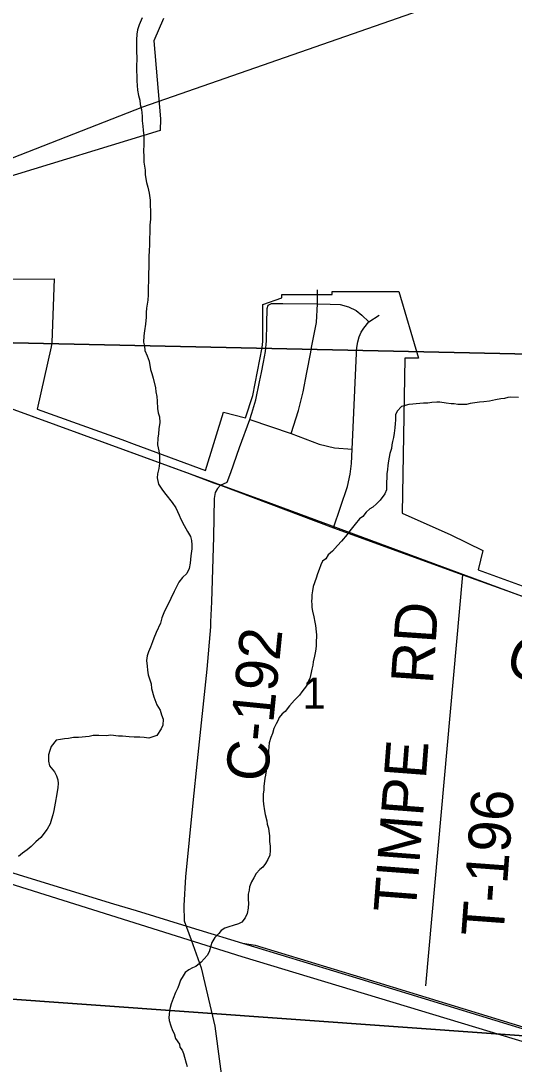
# Model space of a CAD drawing. Extents: x 0 to 34, y 0 to 22.
# Drawn here: x 25.144 to 25.81, y 18.872 to 20.279 of the extents above; entities that cross this region are included whole.
import ezdxf

# ---------------------------------------------------------------- set-up
doc = ezdxf.new("R2010")
doc.units = 0
for name, color, linetype in [('GM_X_City_Street', 7, 'Continuous'), ('GM_X_County_Road', 7, 'Continuous'), ('GM_X_County_Road_Text', 7, 'Continuous'), ('GM_X_Minor_River', 7, 'Continuous'), ('GM_X_Rail_Line', 7, 'Continuous'), ('GM_X_Section', 7, 'Continuous'), ('GM_X_Section_Text', 7, 'Continuous'), ('GM_X_Township_Road', 7, 'Continuous'), ('GM_X_Township_Road_Text', 7, 'Continuous')]:
    doc.layers.add(name, color=color, linetype=linetype)

msp = doc.modelspace()

# ---------------------------------------------------------------- linework, layer by layer
at = {"layer": 'GM_X_City_Street'}
for points in [[(25.3368, 20.282), (25.3235, 20.252), (25.3327, 20.1469), (25.3319, 20.1309), (25.1177, 20.0653)], [(25.1107, 19.9304), (25.1891, 19.9311), (25.186, 19.8449), (25.1851, 19.8393), (25.1663, 19.7552), (25.2805, 19.7144), (25.2972, 19.7081), (25.3934, 19.6725), (25.4177, 19.7511), (25.4472, 19.7433), (25.457, 19.7736), (25.4695, 19.8382), (25.4705, 19.8462), (25.4705, 19.8965), (25.4963, 19.9051), (25.4964, 19.91), (25.5366, 19.91), (25.564, 19.91), (25.564, 19.9138), (25.6541, 19.9138), (25.6804, 19.8237), (25.6621, 19.824), (25.6584, 19.6147), (25.724, 19.5855), (25.7672, 19.5644), (25.7608, 19.5385), (26.0181, 19.4449)]]:
    msp.add_lwpolyline(points, dxfattribs=at)
at = {"layer": 'GM_X_County_Road'}
for points in [[(25.0113, 19.7995), (25.3711, 19.6682), (25.4041, 19.6559)], [(25.4135, 19.6524), (25.4093, 19.648), (25.4061, 19.6427), (25.405, 19.6347), (25.4039, 19.583), (25.4014, 19.4953), (25.4001, 19.4683)], [(25.4041, 19.6559), (25.4135, 19.6524), (25.5658, 19.595)], [(25.5658, 19.595), (25.7402, 19.5316), (26.0796, 19.4097), (26.0866, 19.4072)], [(25.4001, 19.4683), (25.3998, 19.4615), (25.395, 19.4046), (25.3819, 19.2807), (25.3763, 19.2239)], [(25.3763, 19.2239), (25.3665, 19.1241), (25.3639, 19.0857), (25.3644, 19.0648), (25.3738, 19.0391)], [(25.3738, 19.0391), (25.3876, 19.0014), (25.4057, 18.9229), (25.4261, 18.7706), (25.4348, 18.7435), (25.5481, 18.6163), (25.5629, 18.5929), (25.567, 18.4152)]]:
    msp.add_lwpolyline(points, dxfattribs=at)
at = {"layer": 'GM_X_Minor_River'}
for points in [[(25.308, 20.2832), (25.3037, 20.2734), (25.3017, 20.2666), (25.3005, 20.2609), (25.3001, 20.2533), (25.3, 20.245), (25.3003, 20.2389), (25.3005, 20.2279), (25.3, 20.2176), (25.3004, 20.2119), (25.3006, 20.204), (25.3006, 20.1979), (25.3009, 20.1918), (25.3016, 20.1854), (25.303, 20.1781), (25.3045, 20.172), (25.3051, 20.1663), (25.307, 20.1595), (25.308, 20.1504), (25.3079, 20.1439), (25.3086, 20.1367), (25.3093, 20.1314), (25.31, 20.1238), (25.3099, 20.1181), (25.3102, 20.1112), (25.3098, 20.104), (25.31, 20.0953), (25.3103, 20.0885), (25.311, 20.0831), (25.3117, 20.0774), (25.312, 20.0714), (25.3138, 20.0611), (25.3156, 20.0546), (25.3174, 20.0466), (25.3185, 20.0371), (25.3188, 20.0295), (25.3191, 20.0231)], [(25.3191, 20.0231), (25.3189, 20.0113), (25.3181, 20.0033), (25.3178, 19.9756), (25.3173, 19.9699), (25.3168, 19.9597), (25.3167, 19.9468), (25.3162, 19.9381), (25.3159, 19.9092), (25.3154, 19.902), (25.3138, 19.8914), (25.3133, 19.8853), (25.3133, 19.8793), (25.3124, 19.8698), (25.3112, 19.8607), (25.3103, 19.8539), (25.3098, 19.8455), (25.3109, 19.8402), (25.3116, 19.8341), (25.3146, 19.8269), (25.3171, 19.82), (25.3189, 19.8086), (25.3207, 19.8033), (25.3229, 19.7968), (25.3258, 19.7838), (25.3265, 19.7785), (25.3276, 19.7724), (25.3279, 19.766), (25.3286, 19.7561), (25.3296, 19.75), (25.3311, 19.7447), (25.3318, 19.7371), (25.3305, 19.7284), (25.3301, 19.7219), (25.3289, 19.7162), (25.3287, 19.7068), (25.3302, 19.6988), (25.3312, 19.6923), (25.3311, 19.6821), (25.3303, 19.6752), (25.3287, 19.668), (25.3282, 19.6627), (25.33, 19.654), (25.3353, 19.6459), (25.3397, 19.6398), (25.3484, 19.6291), (25.3532, 19.6218), (25.3576, 19.6123), (25.3602, 19.6066), (25.3643, 19.5982), (25.3692, 19.5902), (25.3729, 19.5833), (25.3743, 19.578), (25.375, 19.5723), (25.375, 19.5666), (25.3737, 19.5571), (25.3728, 19.5476), (25.3712, 19.5404), (25.3681, 19.5336), (25.3624, 19.528), (25.3574, 19.5216), (25.3539, 19.5144), (25.3508, 19.5091), (25.3465, 19.4997), (25.3372, 19.4804), (25.3344, 19.4736), (25.3325, 19.4664), (25.3266, 19.454), (25.3235, 19.4464), (25.3216, 19.4411), (25.3192, 19.4339), (25.3165, 19.4279), (25.3145, 19.4222), (25.3137, 19.4161), (25.3147, 19.4085), (25.3151, 19.4032), (25.3161, 19.3968), (25.3198, 19.3846), (25.3205, 19.3785), (25.3237, 19.3671), (25.3278, 19.3564), (25.3319, 19.3491), (25.3341, 19.3427), (25.3363, 19.3369), (25.3355, 19.329), (25.3335, 19.3237), (25.3277, 19.315), (25.317, 19.3113), (25.3106, 19.3122), (25.3049, 19.3126), (25.297, 19.3127), (25.2905, 19.3131), (25.2814, 19.314), (25.2761, 19.314), (25.2655, 19.3153), (25.2594, 19.3146), (25.2492, 19.3151), (25.2416, 19.3148), (25.2363, 19.3137), (25.2222, 19.3123), (25.2154, 19.3124)], [(25.7095, 19.7646), (25.7053, 19.7646), (25.6985, 19.7639), (25.6932, 19.7632), (25.6871, 19.7633), (25.6822, 19.7626), (25.6772, 19.7622), (25.6731, 19.7619), (25.6674, 19.7612), (25.6624, 19.7601), (25.6575, 19.7587), (25.6517, 19.7526), (25.6497, 19.7474), (25.6493, 19.7401), (25.6489, 19.7356), (25.6484, 19.7299), (25.6476, 19.7227), (25.6467, 19.717), (25.6456, 19.7117), (25.6447, 19.7068), (25.6443, 19.7022), (25.6419, 19.6951), (25.6399, 19.6856), (25.6391, 19.6791), (25.6387, 19.6738), (25.6378, 19.6681), (25.6378, 19.664), (25.6373, 19.6552), (25.6372, 19.6465), (25.6349, 19.6408), (25.6287, 19.6322), (25.6237, 19.6273), (25.6191, 19.6228), (25.6149, 19.6206), (25.6099, 19.6161), (25.6053, 19.6104), (25.6011, 19.607), (25.595, 19.5999), (25.5915, 19.5954), (25.588, 19.5912), (25.5842, 19.586), (25.5769, 19.5769), (25.5715, 19.5713), (25.5646, 19.5634), (25.5585, 19.5585), (25.5554, 19.5532), (25.5512, 19.5499), (25.5488, 19.545), (25.5465, 19.5389), (25.5445, 19.5332), (25.5425, 19.5272), (25.5386, 19.5158), (25.5374, 19.5102), (25.5366, 19.5045), (25.5366, 19.5003), (25.5361, 19.4961), (25.5365, 19.4916), (25.5368, 19.4874), (25.5375, 19.4825), (25.5393, 19.4752), (25.5407, 19.468), (25.5414, 19.4631), (25.5425, 19.4547), (25.5428, 19.4505), (25.5427, 19.4395), (25.5423, 19.4353), (25.5414, 19.4285), (25.5402, 19.4221), (25.5386, 19.4145), (25.5378, 19.4099), (25.5366, 19.4046), (25.5358, 19.3997), (25.5338, 19.3918), (25.5315, 19.3869), (25.5295, 19.3819), (25.523, 19.374), (25.5199, 19.3695), (25.5134, 19.3624), (25.5064, 19.3549), (25.5007, 19.3473), (25.4965, 19.3443), (25.4926, 19.3394), (25.491, 19.3349), (25.4887, 19.3308), (25.4856, 19.3243), (25.4836, 19.3175), (25.4813, 19.3122), (25.4793, 19.305), (25.4785, 19.2994), (25.4781, 19.2944), (25.4776, 19.2876), (25.4768, 19.2831), (25.476, 19.277), (25.4755, 19.2728), (25.4751, 19.2671), (25.4743, 19.2614), (25.4735, 19.2573), (25.473, 19.2531), (25.4718, 19.2467), (25.4718, 19.241), (25.471, 19.2364)], [(25.8154, 19.771), (25.8052, 19.7711), (25.801, 19.7708), (25.7964, 19.7697), (25.7915, 19.769), (25.7843, 19.7679), (25.7763, 19.7657), (25.7687, 19.7651), (25.763, 19.7644), (25.7501, 19.7626), (25.7451, 19.7615), (25.7334, 19.7616), (25.7288, 19.7621), (25.7246, 19.7621), (25.7178, 19.7633), (25.7095, 19.7646)], [(25.2154, 19.3124), (25.2085, 19.311), (25.2029, 19.3103), (25.1975, 19.3096), (25.1918, 19.3085), (25.1853, 19.3002), (25.1833, 19.2949), (25.1817, 19.2889), (25.1816, 19.2801), (25.1827, 19.274), (25.1895, 19.266), (25.1924, 19.2607), (25.1943, 19.2553), (25.1946, 19.25), (25.1941, 19.2447), (25.1929, 19.236), (25.1905, 19.2235), (25.1889, 19.2136), (25.1873, 19.2079), (25.1857, 19.2019), (25.1837, 19.1958), (25.1798, 19.1887), (25.1714, 19.1774), (25.1645, 19.1714), (25.158, 19.1654), (25.1526, 19.1609), (25.1465, 19.156), (25.1411, 19.1519)], [(25.471, 19.2364), (25.4709, 19.2319), (25.4712, 19.2273), (25.4716, 19.2224), (25.473, 19.2132), (25.4737, 19.2083), (25.4762, 19.1999), (25.4766, 19.1954), (25.4784, 19.19), (25.4787, 19.1859), (25.4794, 19.1794), (25.4797, 19.1718), (25.4804, 19.1657), (25.4803, 19.1596), (25.4799, 19.1536), (25.4772, 19.1475), (25.4741, 19.1423), (25.4706, 19.1374), (25.4664, 19.134), (25.4618, 19.1287), (25.4583, 19.1227), (25.4552, 19.1174), (25.4528, 19.1106), (25.452, 19.1064), (25.4508, 19.1007), (25.4507, 19.0939), (25.4514, 19.0886), (25.4506, 19.0821), (25.4494, 19.0749), (25.4467, 19.0689), (25.4421, 19.0633), (25.4379, 19.061), (25.4306, 19.0588), (25.4249, 19.0566), (25.4192, 19.0548), (25.4146, 19.0518), (25.4111, 19.0476), (25.4058, 19.0424), (25.4019, 19.0356), (25.4003, 19.0311), (25.398, 19.0231), (25.3956, 19.0182), (25.3872, 19.0092), (25.3803, 19.0032), (25.3757, 19.0013), (25.3708, 18.9987), (25.3658, 18.9954), (25.3631, 18.9905), (25.3596, 18.9848), (25.3576, 18.9795), (25.3561, 18.9746), (25.3526, 18.9682), (25.3498, 18.9602), (25.3471, 18.9531), (25.3455, 18.9481), (25.3447, 18.944), (25.3443, 18.9387), (25.3439, 18.9345), (25.3442, 18.9303), (25.3464, 18.9231), (25.3486, 18.917), (25.3508, 18.9128), (25.353, 18.9063), (25.3582, 18.8987), (25.3586, 18.8945), (25.3616, 18.8903), (25.3634, 18.8861), (25.3649, 18.8811), (25.3674, 18.8731), (25.3685, 18.8682)]]:
    msp.add_lwpolyline(points, dxfattribs=at)
at = {"layer": 'GM_X_Rail_Line'}
for points in [[(24.6857, 19.9193), (25.3089, 20.1629), (25.713, 20.3036), (25.9724, 20.3916), (26.54, 20.6067), (26.7751, 20.7), (27.3361, 20.9)], [(24.6857, 19.9193), (25.0148, 19.7985), (25.4772, 19.6296), (26.0332, 19.4244), (26.618, 19.2083), (27.1754, 19.0083), (27.8265, 18.7785), (28.397, 18.5695), (29.2915, 18.2251), (29.5147, 18.1387)], [(24.1704, 19.5327), (24.2425, 19.4909), (24.3878, 19.4135), (24.5787, 19.3195), (24.7175, 19.2589), (24.8405, 19.2105), (24.9746, 19.1639), (25.4423, 19.0168), (26.3104, 18.7542), (27.1506, 18.4971), (27.9899, 18.2401), (28.4862, 18.088)], [(25.1011, 19.1396), (25.1536, 19.1235), (25.2694, 19.0879), (25.2996, 19.0787), (25.3683, 19.0577), (25.4595, 19.0299), (25.6015, 18.9867), (25.8055, 18.9242), (25.847, 18.9114), (25.9704, 18.8734), (26.0653, 18.8446), (26.2947, 18.7744), (26.4597, 18.7238), (26.5651, 18.6918), (26.6458, 18.6671), (26.7252, 18.6428), (26.8299, 18.611), (26.9128, 18.5857), (26.9875, 18.5627), (27.1965, 18.4991)], [(25.4438, 19.0347), (25.4601, 19.0321), (25.6021, 18.989), (25.8062, 18.9265), (25.8477, 18.9137), (25.9711, 18.8756), (26.066, 18.8468), (26.2954, 18.7766), (26.4604, 18.726), (26.5658, 18.694), (26.6465, 18.6693), (26.6813, 18.6587), (26.7055, 18.6488)]]:
    msp.add_lwpolyline(points, dxfattribs=at)
at = {"layer": 'GM_X_Section'}
for points in [[(26.1064, 20.8349), (26.1071, 20.822), (26.0975, 19.8234), (25.0925, 19.8455), (25.1198, 20.8277)], [(25.0077, 19.8483), (25.0925, 19.8455), (26.0975, 19.8234), (26.0616, 18.9227), (26.0607, 18.8928), (24.9624, 18.9716)], [(26.0607, 18.8928), (26.0171, 17.9156), (26.0158, 17.891), (24.9267, 17.9117), (24.9624, 18.9716)]]:
    msp.add_lwpolyline(points, close=True, dxfattribs=at)
at = {"layer": 'GM_X_Township_Road'}
msp.add_line((25.6906, 18.9772), (25.7402, 19.5316), dxfattribs=at)
for points in [[(25.5352, 19.8319), (25.5364, 19.8383), (25.543, 19.8722), (25.5443, 19.8971), (25.5442, 19.9162)], [(25.4687, 19.8047), (25.4715, 19.8183), (25.4741, 19.8331), (25.4757, 19.8473), (25.4762, 19.8705), (25.4763, 19.8908), (25.4778, 19.8956)], [(25.4778, 19.8956), (25.4824, 19.8975), (25.4974, 19.8978), (25.5443, 19.8971), (25.5612, 19.8968), (25.5747, 19.8961), (25.5861, 19.8931), (25.5964, 19.8881), (25.6043, 19.882), (25.6135, 19.873)], [(25.5971, 19.8335), (25.5974, 19.8383), (25.5985, 19.8461), (25.6007, 19.8529), (25.6034, 19.859), (25.6066, 19.8643), (25.6135, 19.873), (25.6275, 19.882)], [(25.5086, 19.7222), (25.5186, 19.7531), (25.5248, 19.7783), (25.5298, 19.8045), (25.5352, 19.8319)], [(25.5658, 19.595), (25.5849, 19.6509), (25.5882, 19.6674), (25.5902, 19.6816), (25.591, 19.7013), (25.5919, 19.7203), (25.5945, 19.7809), (25.5969, 19.8307), (25.5971, 19.8335)], [(25.4135, 19.6524), (25.4223, 19.6565), (25.4273, 19.6699), (25.4393, 19.7033), (25.453, 19.741), (25.4558, 19.7496), (25.4612, 19.7678), (25.4662, 19.7921), (25.4687, 19.8047)], [(25.453, 19.741), (25.5086, 19.7222), (25.5467, 19.7079), (25.5674, 19.703), (25.591, 19.7013)]]:
    msp.add_lwpolyline(points, dxfattribs=at)

# ---------------------------------------------------------------- texts
at = {"layer": 'GM_X_County_Road_Text'}
for s, rotation, p in [('C-192', 84.2806, (25.4766, 19.251)), ('C-20', 341.1304, (25.7946, 19.4002))]:
    msp.add_text(s, height=0.05682, rotation=rotation, dxfattribs=at).set_placement(p)
at = {"layer": 'GM_X_Section_Text'}
msp.add_text('1', height=0.0419, rotation=0, dxfattribs=at).set_placement((25.524, 19.3512))
at = {"layer": 'GM_X_Township_Road_Text'}
for s, rotation, p in [('RD', 86.0551, (25.6999, 19.3835)), ('TIMPE', 85.6371, (25.6766, 19.0745)), ('T-196', 85.7948, (25.7949, 19.0422))]:
    msp.add_text(s, height=0.05682, rotation=rotation, dxfattribs=at).set_placement(p)

doc.saveas('drawing.dxf')
